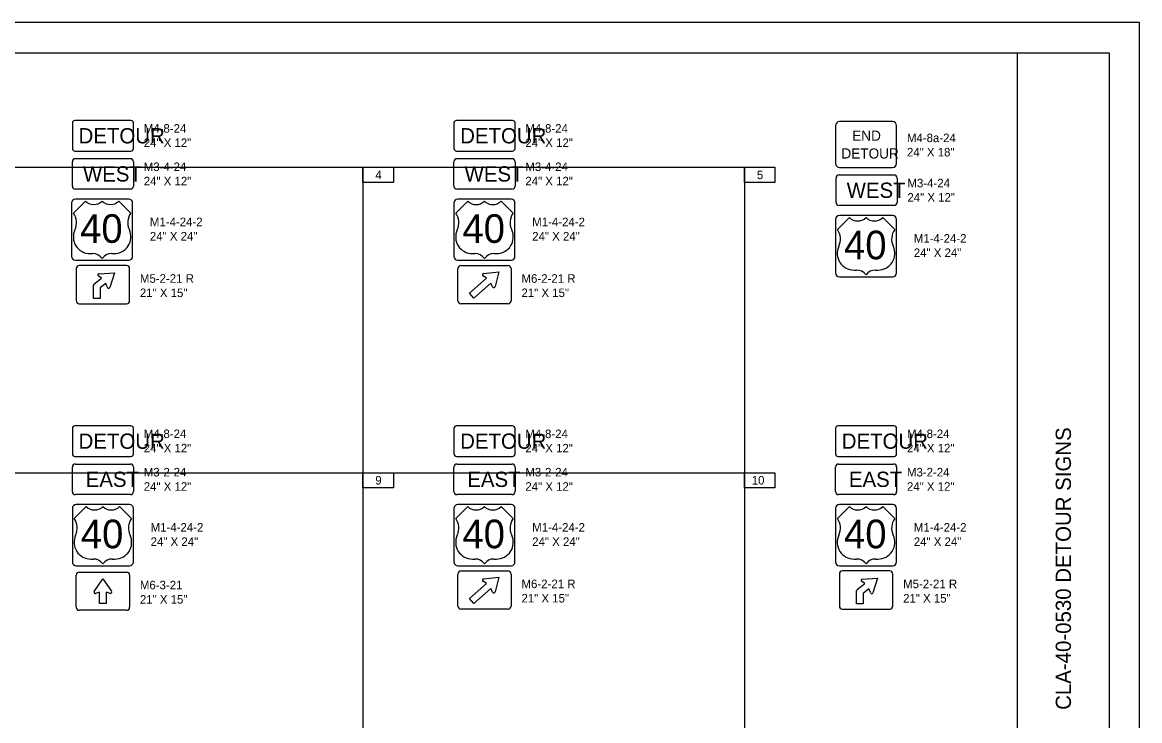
# Model space of a CAD drawing. Extents: x 0 to 714, y 0 to 440.
# Drawn here: x 314 to 680, y 211.4 to 440 of the extents above; entities that cross this region are included whole.
import ezdxf

# ---------------------------------------------------------------- set-up
doc = ezdxf.new("R2010")
doc.units = 0
for name, color, linetype in [('SC_Scratch1', 7, 'Continuous'), ('SH_Border', 7, 'Continuous'), ('SH_Cut_Line', 7, 'Continuous'), ('SH_Data', 7, 'Continuous'), ('SH_Text', 7, 'Continuous'), ('SN_P_Signs', 7, 'Continuous'), ('SN_P_Text', 7, 'Continuous')]:
    doc.layers.add(name, color=color, linetype=linetype)

msp = doc.modelspace()

# ---------------------------------------------------------------- linework, layer by layer
at = {"layer": 'SC_Scratch1'}
for p, q in [((225.54, 392.53), (375.54, 392.53)), ((375.54, 392.53), (550.54, 392.53)), ((425.54, 392.53), (425.54, 292.53)), ((550.54, 392.53), (550.54, 292.53)), ((225.54, 292.53), (375.54, 292.53)), ((375.54, 292.53), (550.54, 292.53)), ((425.54, 292.53), (425.54, 192.53)), ((550.54, 292.53), (550.54, 192.53))]:
    msp.add_line(p, q, dxfattribs=at)
at = {"layer": 'SH_Border'}
msp.add_line((640, 10), (640, 430), dxfattribs=at)
msp.add_lwpolyline([(30, 430), (670, 430), (670, 10), (30, 10)], close=True, dxfattribs=at)
at = {"layer": 'SH_Cut_Line'}
msp.add_lwpolyline([(0, 0), (680, 0), (680, 440), (0, 440)], close=True, dxfattribs=at)
at = {"layer": 'SH_Text'}
for points in [[(425.54, 392.53), (435.54, 392.53), (435.54, 387.53), (425.54, 387.53)], [(550.54, 392.53), (560.54, 392.53), (560.54, 387.53), (550.54, 387.53)], [(425.54, 292.53), (435.54, 292.53), (435.54, 287.53), (425.54, 287.53)], [(550.54, 292.53), (560.54, 292.53), (560.54, 287.53), (550.54, 287.53)]]:
    msp.add_lwpolyline(points, close=True, dxfattribs=at)
at = {"layer": 'SN_P_Signs'}
for p, q in [((331.39, 395.37), (349.39, 395.37)), ((456.39, 395.37), (474.39, 395.37)), ((330.39, 386.37), (330.39, 394.37)), ((350.39, 394.37), (350.39, 386.37)), ((455.39, 386.37), (455.39, 394.37)), ((475.39, 394.37), (475.39, 386.37)), ((580.55, 381.03), (580.55, 389.03)), ((581.55, 390.03), (599.55, 390.03)), ((600.55, 389.03), (600.55, 381.03)), ((349.39, 385.37), (331.39, 385.37)), ((474.39, 385.37), (456.39, 385.37)), ((334.66, 381.47), (330.76, 377.57)), ((349.51, 377.57), (345.6, 381.47)), ((459.91, 381.46), (456, 377.55)), ((474.75, 377.55), (470.85, 381.46)), ((599.55, 380.03), (581.55, 380.03)), ((584.91, 376.08), (581, 372.18)), ((599.75, 372.18), (595.85, 376.08)), ((336.23, 364.28), (337.01, 364.28)), ((343.26, 364.28), (344.04, 364.28)), ((461.47, 364.27), (462.25, 364.27)), ((468.5, 364.27), (469.28, 364.27)), ((331.64, 359.37), (331.64, 348.87)), ((348.14, 360.37), (332.64, 360.37)), ((349.14, 348.87), (349.14, 359.37)), ((456.64, 348.86), (456.64, 359.36)), ((457.64, 360.36), (473.14, 360.36)), ((474.14, 359.36), (474.14, 348.86)), ((586.47, 358.9), (587.25, 358.9)), ((593.5, 358.9), (594.28, 358.9)), ((337.45, 354.26), (339.97, 356.24)), ((339.97, 356.24), (338.86, 356.99)), ((339.13, 357.7), (344.14, 358.01)), ((339.13, 357.7), (339.13, 357.7)), ((344.14, 358.01), (342.63, 353.22)), ((460.45, 351.34), (466.07, 356.26)), ((466.07, 356.26), (464.92, 356.97)), ((465.09, 357.74), (470.08, 358.33)), ((465.09, 357.74), (465.09, 357.74)), ((470.08, 358.33), (468.85, 353.54)), ((337.26, 349.59), (337.26, 353.89)), ((339.45, 352.9), (339.45, 349.59)), ((341.32, 354.51), (339.57, 353.14)), ((341.81, 353.35), (341.32, 354.51)), ((467.51, 354.62), (461.89, 349.69)), ((468.05, 353.39), (467.51, 354.62)), ((332.64, 347.87), (348.14, 347.87)), ((339.45, 349.59), (337.26, 349.59)), ((473.14, 347.86), (457.64, 347.86)), ((461.89, 349.69), (460.45, 351.34)), ((330.39, 286.37), (330.39, 294.37)), ((331.39, 295.37), (349.39, 295.37)), ((350.39, 294.37), (350.39, 286.37)), ((455.39, 286.37), (455.39, 294.37)), ((456.39, 295.37), (474.39, 295.37)), ((475.39, 294.37), (475.39, 286.37)), ((580.39, 286.37), (580.39, 294.37)), ((581.39, 295.37), (599.39, 295.37)), ((600.39, 294.37), (600.39, 286.37)), ((349.39, 285.37), (331.39, 285.37)), ((474.39, 285.37), (456.39, 285.37)), ((599.39, 285.37), (581.39, 285.37)), ((334.91, 281.46), (331, 277.55)), ((349.75, 277.55), (345.85, 281.46)), ((459.91, 281.46), (456, 277.55)), ((474.75, 277.55), (470.85, 281.46)), ((584.91, 281.46), (581, 277.55)), ((599.75, 277.55), (595.85, 281.46)), ((336.47, 264.27), (337.25, 264.27)), ((343.5, 264.27), (344.28, 264.27)), ((461.47, 264.27), (462.25, 264.27)), ((468.5, 264.27), (469.28, 264.27)), ((586.47, 264.27), (587.25, 264.27)), ((593.5, 264.27), (594.28, 264.27)), ((332.64, 259.99), (348.14, 259.99)), ((457.64, 260.36), (473.14, 260.36)), ((598.14, 260.36), (582.64, 260.36)), ((331.64, 248.49), (331.64, 258.99)), ((337.54, 253.66), (340.39, 257.8)), ((340.39, 257.8), (343.18, 253.72)), ((349.14, 258.99), (349.14, 248.49)), ((456.64, 248.86), (456.64, 259.36)), ((460.45, 251.34), (466.07, 256.26)), ((466.07, 256.26), (464.92, 256.97)), ((465.09, 257.74), (470.08, 258.33)), ((465.09, 257.74), (465.09, 257.74)), ((470.08, 258.33), (468.85, 253.54)), ((474.14, 259.36), (474.14, 248.86)), ((581.64, 259.36), (581.64, 248.86)), ((587.45, 254.25), (589.97, 256.23)), ((589.97, 256.23), (588.86, 256.98)), ((589.13, 257.69), (594.14, 258)), ((589.13, 257.69), (589.13, 257.69)), ((594.14, 258), (592.63, 253.21)), ((599.14, 248.86), (599.14, 259.36)), ((339.29, 253.42), (338.01, 253.03)), ((339.29, 249.67), (339.29, 253.42)), ((342.76, 253.03), (341.48, 253.42)), ((341.48, 253.42), (341.48, 249.67)), ((467.51, 254.62), (461.89, 249.69)), ((468.05, 253.39), (467.51, 254.62)), ((587.27, 249.58), (587.27, 253.88)), ((589.45, 252.88), (589.45, 249.58)), ((591.32, 254.5), (589.58, 253.13)), ((591.82, 253.34), (591.32, 254.5)), ((341.48, 249.67), (339.29, 249.67)), ((461.89, 249.69), (460.45, 251.34)), ((589.45, 249.58), (587.27, 249.58)), ((348.14, 247.49), (332.64, 247.49)), ((473.14, 247.86), (457.64, 247.86)), ((582.64, 247.86), (598.14, 247.86))]:
    msp.add_line(p, q, dxfattribs=at)
for points in [[(330.39, 407.07), (330.39, 398.67)], [(349.59, 407.87), (331.19, 407.87)], [(350.39, 398.67), (350.39, 407.07)], [(455.39, 407.07), (455.39, 398.67)], [(474.59, 407.87), (456.19, 407.87)], [(475.39, 398.67), (475.39, 407.07)], [(599.09, 407.49), (581.69, 407.49)], [(580.39, 406.19), (580.39, 393.79)], [(600.39, 393.79), (600.39, 406.19)], [(331.19, 397.87), (349.59, 397.87)], [(456.19, 397.87), (474.59, 397.87)], [(581.69, 392.49), (599.09, 392.49)], [(330.13, 380.85), (330.13, 363.35)], [(348.88, 382.1), (331.38, 382.1)], [(350.13, 363.35), (350.13, 380.85)], [(455.38, 380.84), (455.38, 363.34)], [(474.13, 382.09), (456.63, 382.09)], [(475.38, 363.34), (475.38, 380.84)], [(580.38, 375.46), (580.38, 357.96)], [(599.13, 376.71), (581.63, 376.71)], [(600.38, 357.96), (600.38, 375.46)], [(331.38, 362.1), (348.88, 362.1)], [(456.63, 362.09), (474.13, 362.09)], [(581.63, 356.71), (599.13, 356.71)], [(349.59, 307.87), (331.19, 307.87)], [(474.59, 307.87), (456.19, 307.87)], [(599.59, 307.87), (581.19, 307.87)], [(330.39, 307.07), (330.39, 298.67)], [(350.39, 298.67), (350.39, 307.07)], [(455.39, 307.07), (455.39, 298.67)], [(475.39, 298.67), (475.39, 307.07)], [(580.39, 307.07), (580.39, 298.67)], [(600.39, 298.67), (600.39, 307.07)], [(331.19, 297.87), (349.59, 297.87)], [(456.19, 297.87), (474.59, 297.87)], [(581.19, 297.87), (599.59, 297.87)], [(349.13, 282.09), (331.63, 282.09)], [(474.13, 282.09), (456.63, 282.09)], [(599.13, 282.09), (581.63, 282.09)], [(330.38, 280.84), (330.38, 263.34)], [(350.38, 263.34), (350.38, 280.84)], [(455.38, 280.84), (455.38, 263.34)], [(475.38, 263.34), (475.38, 280.84)], [(580.38, 280.84), (580.38, 263.34)], [(600.38, 263.34), (600.38, 280.84)], [(331.63, 262.09), (349.13, 262.09)], [(456.63, 262.09), (474.13, 262.09)], [(581.63, 262.09), (599.13, 262.09)]]:
    msp.add_lwpolyline(points, dxfattribs=at)
for centre, radius, start, end in [((331.19, 407.07), 0.8, 90, 180), ((349.59, 407.07), 0.8, 0, 90), ((456.19, 407.07), 0.8, 90, 180), ((474.59, 407.07), 0.8, 0, 90), ((581.69, 406.19), 1.3, 90, 180), ((599.09, 406.19), 1.3, 0, 90), ((331.19, 398.67), 0.8, 180, 270), ((331.39, 394.36), 1, 90, 180), ((349.39, 394.36), 1, 0, 90), ((349.59, 398.67), 0.8, 270, 0), ((456.19, 398.67), 0.8, 180, 270), ((456.39, 394.36), 1, 90, 180), ((474.39, 394.36), 1, 0, 90), ((474.59, 398.67), 0.8, 270, 0), ((581.69, 393.79), 1.3, 180, 270), ((599.09, 393.79), 1.3, 270, 0), ((581.55, 389.03), 1, 90, 180), ((599.55, 389.03), 1, 0, 90), ((331.39, 386.36), 1, 180, 270), ((349.39, 386.36), 1, 270, 0), ((456.39, 386.36), 1, 180, 270), ((474.39, 386.36), 1, 270, 0), ((331.38, 380.85), 1.25, 90, 180), ((337.4, 384.26), 3.91, 225.573, 314.427), ((342.87, 384.26), 3.91, 225.573, 314.427), ((348.88, 380.85), 1.25, 0, 90), ((456.63, 380.84), 1.25, 90, 180), ((462.64, 384.25), 3.91, 225.573, 314.427), ((468.11, 384.25), 3.91, 225.573, 314.427), ((474.13, 380.84), 1.25, 0, 90), ((581.55, 381.03), 1, 180, 270), ((599.55, 381.03), 1, 270, 0), ((326.28, 374.43), 5.47, 334.5471, 35.0009), ((353.99, 374.43), 5.47, 144.9991, 205.4529), ((451.52, 374.42), 5.47, 334.5471, 35.0009), ((479.23, 374.42), 5.47, 144.9991, 205.4529), ((581.63, 375.46), 1.25, 90, 180), ((587.64, 378.87), 3.91, 225.573, 314.427), ((593.11, 378.87), 3.91, 225.573, 314.427), ((599.13, 375.46), 1.25, 0, 90), ((336.17, 369.75), 5.47, 154.8319, 270.6383), ((344.1, 369.75), 5.47, 269.3617, 25.1681), ((461.41, 369.74), 5.47, 154.8319, 270.6383), ((469.35, 369.74), 5.47, 269.3617, 25.1681), ((576.52, 369.04), 5.47, 334.5471, 35.0009), ((604.23, 369.04), 5.47, 144.9991, 205.4529), ((586.41, 364.36), 5.47, 154.8319, 270.6383), ((594.35, 364.36), 5.47, 269.3617, 25.1681), ((331.38, 363.35), 1.25, 180, 270), ((337.01, 360.38), 3.91, 36.8699, 90), ((343.26, 360.38), 3.91, 90, 143.1301), ((348.88, 363.35), 1.25, 270, 0), ((456.63, 363.34), 1.25, 180, 270), ((462.25, 360.37), 3.91, 36.8699, 90), ((468.5, 360.37), 3.91, 90, 143.1301), ((474.13, 363.34), 1.25, 270, 0), ((332.64, 359.37), 1, 90, 180), ((348.14, 359.37), 1, 0, 90), ((457.64, 359.36), 1, 90, 180), ((473.14, 359.36), 1, 0, 90), ((587.25, 354.99), 3.91, 36.8699, 90), ((593.5, 354.99), 3.91, 90, 143.1301), ((339.15, 357.29), 0.417, 93.5999, 225.0001), ((465.14, 357.32), 0.417, 96.6699, 238.4633), ((581.63, 357.96), 1.25, 180, 270), ((599.13, 357.96), 1.25, 270, 0), ((337.73, 353.89), 0.468, 127.7857, 180), ((339.76, 352.9), 0.312, 127.3494, 180), ((342.23, 353.35), 0.417, 180.0509, 342.5804), ((468.43, 353.56), 0.417, 204.0541, 356.2683), ((332.64, 348.87), 1, 180, 270), ((348.14, 348.87), 1, 270, 360), ((457.64, 348.86), 1, 180, 270), ((473.14, 348.86), 1, 270, 0), ((331.19, 307.07), 0.8, 90, 180), ((349.59, 307.07), 0.8, 0, 90), ((456.19, 307.07), 0.8, 90, 180), ((474.59, 307.07), 0.8, 0, 90), ((581.19, 307.07), 0.8, 90, 180), ((599.59, 307.07), 0.8, 0, 90), ((331.19, 298.67), 0.8, 180, 270), ((349.59, 298.67), 0.8, 270, 0), ((456.19, 298.67), 0.8, 180, 270), ((474.59, 298.67), 0.8, 270, 0), ((581.19, 298.67), 0.8, 180, 270), ((599.59, 298.67), 0.8, 270, 0), ((331.39, 294.36), 1, 90, 180), ((349.39, 294.36), 1, 0, 90), ((456.39, 294.36), 1, 90, 180), ((474.39, 294.36), 1, 0, 90), ((581.39, 294.36), 1, 90, 180), ((599.39, 294.36), 1, 0, 90), ((331.39, 286.36), 1, 180, 270), ((349.39, 286.36), 1, 270, 0), ((456.39, 286.36), 1, 180, 270), ((474.39, 286.36), 1, 270, 0), ((581.39, 286.36), 1, 180, 270), ((599.39, 286.36), 1, 270, 0), ((331.63, 280.84), 1.25, 90, 180), ((349.13, 280.84), 1.25, 0, 90), ((456.63, 280.84), 1.25, 90, 180), ((474.13, 280.84), 1.25, 0, 90), ((581.63, 280.84), 1.25, 90, 180), ((599.13, 280.84), 1.25, 0, 90), ((337.64, 284.25), 3.91, 225.573, 314.427), ((343.11, 284.25), 3.91, 225.573, 314.427), ((462.64, 284.25), 3.91, 225.573, 314.427), ((468.11, 284.25), 3.91, 225.573, 314.427), ((587.64, 284.25), 3.91, 225.573, 314.427), ((593.11, 284.25), 3.91, 225.573, 314.427), ((326.52, 274.42), 5.47, 334.5471, 35.0009), ((354.23, 274.42), 5.47, 144.9991, 205.4529), ((451.52, 274.42), 5.47, 334.5471, 35.0009), ((479.23, 274.42), 5.47, 144.9991, 205.4529), ((576.52, 274.42), 5.47, 334.5471, 35.0009), ((604.23, 274.42), 5.47, 144.9991, 205.4529), ((336.41, 269.74), 5.47, 154.8319, 270.6383), ((344.35, 269.74), 5.47, 269.3617, 25.1681), ((461.41, 269.74), 5.47, 154.8319, 270.6383), ((469.35, 269.74), 5.47, 269.3617, 25.1681), ((586.41, 269.74), 5.47, 154.8319, 270.6383), ((594.35, 269.74), 5.47, 269.3617, 25.1681), ((337.25, 260.37), 3.91, 36.8699, 90), ((343.5, 260.37), 3.91, 90, 143.1301), ((462.25, 260.37), 3.91, 36.8699, 90), ((468.5, 260.37), 3.91, 90, 143.1301), ((587.25, 260.37), 3.91, 36.8699, 90), ((593.5, 260.37), 3.91, 90, 143.1301), ((331.63, 263.34), 1.25, 180, 270), ((332.64, 258.99), 1, 90, 180), ((348.14, 258.99), 1, 0, 90), ((349.13, 263.34), 1.25, 270, 0), ((456.63, 263.34), 1.25, 180, 270), ((457.64, 259.36), 1, 90, 180), ((473.14, 259.36), 1, 0, 90), ((474.13, 263.34), 1.25, 270, 0), ((581.63, 263.34), 1.25, 180, 270), ((582.64, 259.36), 1, 90, 180), ((598.14, 259.36), 1, 0, 90), ((599.13, 263.34), 1.25, 270, 0), ((465.14, 257.32), 0.417, 96.6699, 238.4633), ((589.15, 257.27), 0.417, 93.5999, 225.0001), ((337.89, 253.43), 0.417, 145.4112, 287.2046), ((342.89, 253.43), 0.417, 252.7954, 45.0096), ((468.43, 253.56), 0.417, 204.0541, 356.2683), ((587.73, 253.88), 0.468, 127.7857, 180), ((589.76, 252.88), 0.312, 127.3494, 180), ((592.23, 253.34), 0.417, 180.0509, 342.5804), ((332.64, 248.49), 1, 180, 270), ((348.14, 248.49), 1, 270, 0), ((457.64, 248.86), 1, 180, 270), ((473.14, 248.86), 1, 270, 0), ((582.64, 248.86), 1, 180, 270), ((598.14, 248.86), 1, 270, 360)]:
    msp.add_arc(centre, radius, start, end, dxfattribs=at)

# ---------------------------------------------------------------- texts
at = {"layer": 'SH_Data'}
msp.add_text('CLA-40-0530 DETOUR SIGNS', height=5, rotation=90, dxfattribs=at).set_placement((657.5, 214.88))
at = {"layer": 'SH_Text'}
for s, p in [('4', (429.63, 388.66)), ('5', (554.63, 388.66)), ('9', (429.63, 288.66)), ('10', (552.93, 288.66))]:
    msp.add_text(s, height=2.8, dxfattribs=at).set_placement(p)
at = {"layer": 'SN_P_Signs'}
for s, height, p in [('DETOUR', 5, (332.42, 400.37)), ('DETOUR', 5, (457.42, 400.37)), ('END', 3.333, (585.83, 401.22)), ('DETOUR', 3.333, (582.29, 395.4)), ('WEST', 5, (333.86, 387.87)), ('WEST', 5, (458.86, 387.87)), ('WEST', 5, (584.02, 382.53)), ('40', 9.375, (332.91, 367.8)), ('40', 9.375, (458.15, 367.79)), ('40', 9.375, (583.15, 362.41)), ('DETOUR', 5, (332.42, 300.37)), ('DETOUR', 5, (457.42, 300.37)), ('DETOUR', 5, (582.42, 300.37)), ('EAST', 5, (334.75, 287.87)), ('EAST', 5, (459.75, 287.87)), ('EAST', 5, (584.75, 287.87)), ('40', 9.375, (333.15, 267.79)), ('40', 9.375, (458.15, 267.79)), ('40', 9.375, (583.15, 267.79))]:
    msp.add_text(s, height=height, dxfattribs=at).set_placement(p)
at = {"layer": 'SN_P_Text'}
for s, p in [('M4-8-24', (353.77, 403.87)), ('M4-8-24', (478.77, 403.87)), ('M4-8a-24', (603.77, 400.78)), ('24" X 12"', (353.77, 399.18)), ('24" X 12"', (478.77, 399.18)), ('24" X 18"', (603.77, 396.09)), ('M3-4-24', (353.77, 391.31)), ('M3-4-24', (478.77, 391.31)), ('24" X 12"', (353.77, 386.62)), ('24" X 12"', (478.77, 386.62)), ('M3-4-24', (603.93, 385.98)), ('24" X 12"', (603.93, 381.29)), ('M1-4-24-2', (355.78, 373.26)), ('M1-4-24-2', (481.02, 373.25)), ('24" X 24"', (355.78, 368.57)), ('24" X 24"', (481.02, 368.56)), ('M1-4-24-2', (606.02, 367.87)), ('24" X 24"', (606.02, 363.18)), ('M5-2-21 R', (352.51, 354.73)), ('M6-2-21 R', (477.51, 354.73)), ('21" X 15"', (352.51, 350.04)), ('21" X 15"', (477.51, 350.04)), ('M4-8-24', (353.77, 303.87)), ('M4-8-24', (478.77, 303.87)), ('M4-8-24', (603.77, 303.87)), ('24" X 12"', (353.77, 299.18)), ('24" X 12"', (478.77, 299.18)), ('24" X 12"', (603.77, 299.18)), ('M3-2-24', (353.77, 291.31)), ('M3-2-24', (478.77, 291.31)), ('M3-2-24', (603.77, 291.31)), ('24" X 12"', (353.77, 286.62)), ('24" X 12"', (478.77, 286.62)), ('24" X 12"', (603.77, 286.62)), ('M1-4-24-2', (356.02, 273.25)), ('M1-4-24-2', (481.02, 273.25)), ('M1-4-24-2', (606.02, 273.25)), ('24" X 24"', (356.02, 268.56)), ('24" X 24"', (481.02, 268.56)), ('24" X 24"', (606.02, 268.56)), ('M6-3-21', (352.51, 254.35)), ('M6-2-21 R', (477.51, 254.73)), ('M5-2-21 R', (602.52, 254.72)), ('21" X 15"', (477.51, 250.04)), ('21" X 15"', (602.52, 250.03)), ('21" X 15"', (352.51, 249.66))]:
    msp.add_text(s, height=2.8, dxfattribs=at).set_placement(p)

doc.saveas('drawing.dxf')
